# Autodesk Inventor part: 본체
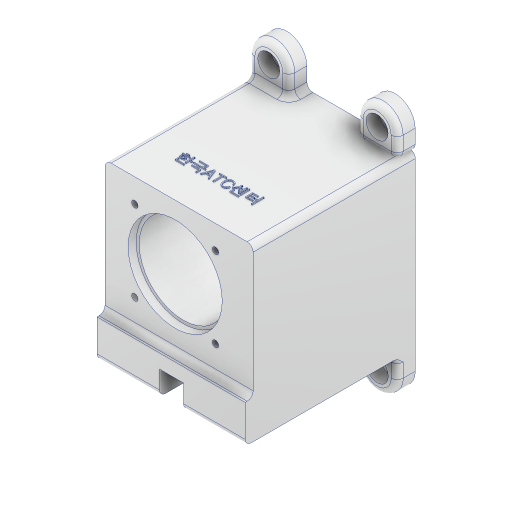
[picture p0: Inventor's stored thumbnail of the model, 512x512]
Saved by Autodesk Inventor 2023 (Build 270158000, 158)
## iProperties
Created: 2024-11
Part Number: 본체
Material: 알루미늄 6061
Document SubType Name: Modeling
Designer: home
Density: 2.7 g/cm^3
Appearance: 알루미늄 - 평지
Mass: 1097.44 g
Surface Area: 539.9 cm^2
Volume: 406.46 cm^3
Author: home
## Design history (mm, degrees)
sketch "스케치10"
  geometry: L1 (-37, 42.5)-(37, 42.5); L2 (37, 42.5)-(37, -42.5); L3 (37, -42.5)-(-37, -42.5); L4 (-37, -42.5)-(-37, 42.5); L5 (-37, 42.5)-(37, -42.5); L6 (37, 42.5)-(-37, -42.5); 1 further point
  constraints: 12 end point, 2 midpoint, 2 parallel, 1 horizontal, 1 perpendicular
  dimensions: "d43" = 74 distance of L1.start L1.end; "d44" = 85 distance of L3.end L1.start
extrude "돌출8" new body sketch "스케치10" stored distance "d45" = 85; taper "d46" = 0 deg
sketch "스케치11"
  geometry: L1 (85, 85)-(0, 85) reference; L2 (0, 0)-(0, 85) reference; L3 (0, 85)-(4, 85); L4 (4, 85)-(4, 19); L5 (4, 19)-(0, 19); L6 (0, 19)-(0, 85); L7 (0, 85)-(4, 19); L8 (4, 85)-(0, 19); 4 further points
  constraints: 12 end point, 2 midpoint, 2 parallel, 1 horizontal, 1 perpendicular
  dimensions: "d47" = 4 distance of L1.end L3.end; "d48" = 66 distance of L3.end L4.end
extrude "돌출9" cut sketch "스케치11" distance "d49" = 77; taper "d50" = 0 deg
sketch "스케치31"
  geometry: C1 r 23.5 at (35.036, 34.068); 1 further point
  constraints: 1 centre point
  dimensions: "d164" = 47 diameter of C1
extrude "돌출21" cut sketch "스케치31" distance "d165" = 4; taper "d166" = 0 deg
sketch "스케치32"
  geometry: C1 r 23.5 at (0, 0) reference; C2 r 22 at (0, 0); 1 further point
  constraints: 1 centre point, 1 coincident
  dimensions: "d168" = 44 diameter of C2
extrude "돌출22" cut sketch "스케치32" distance "d169" = 40; taper "d170" = 0 deg
sketch "스케치35"
  geometry: C1 r 22 at (0, 0) reference; C2 r 17.5 at (0, 0); 1 further point
  constraints: 1 centre point, 1 coincident
  dimensions: "d175" = 35 diameter of C2
extrude "돌출24" cut sketch "스케치35" distance "d176" = 11; taper "d177" = 0 deg
sketch "스케치38"
  geometry: L1 (37, -42.5)-(37, 42.5) reference; L2 (-16.907, 52.568)-(-16.907, 42.568); L3 (-16.907, 42.568)-(-36.907, 42.568); L4 (-36.907, 42.568)-(-36.907, 52.568); L5 (-16.907, 62.568)-(-36.907, 42.568); L6 (-36.907, 62.568)-(-26.907, 52.568); L7 (-19.836, 45.497)-(-16.907, 42.568); L8 (37, 42.5)-(-37, 42.5) reference; L9 (37, 62.5)-(37.204, 62.5); L10 (37.204, 52.5)-(37.204, 42.5); L11 (37.204, 42.5)-(17.204, 42.5); L12 (17.204, 42.5)-(17.204, 52.5); L13 (17.204, 62.5)-(37.204, 42.5); L14 (37.204, 62.5)-(17.204, 42.5); A1 r 10 centre (-26.907, 52.568) between (-16.907, 52.568) and (-36.907, 52.568); A2 r 10 centre (27.204, 52.5) between (37.204, 52.5) and (17.204, 52.5); A3 r 10 centre (27.204, 52.5) between (26.037, 42.568) and (27.204, 42.5); 4 further points
  constraints: 24 end point, 6 point on circle, 5 midpoint, 3 centre point, 3 parallel, 3 point on line, 2 coincident, 1 horizontal, 1 perpendicular
  dimensions: "d194" = 20 distance of L6.start L5.start; "d195" = 20 distance of L5.start L2.end; "d196" = 20 diameter of A1; "d197" = 20 distance of L13.start L9.end; "d198" = 20 distance of L9.end L10.end
sketch "스케치36"
  geometry: C1 r 17.5 at (0, 0) reference; C2 r 15 at (0, 0); 1 further point
  constraints: 1 centre point, 1 coincident
  dimensions: "d178" = 30 diameter of C2
extrude "돌출25" cut sketch "스케치36" distance "d179" = 4; taper "d180" = 0 deg
sketch "스케치37"
  geometry: L1 (35.036, 62.568)-(35.036, 5.568); L2 (35.036, 34.068)-(14.884, 54.22); L3 (35.036, 34.068)-(55.189, 54.22); L4 (35.036, 34.068)-(14.884, 13.915); L5 (35.036, 34.068)-(55.624, 13.48); C1 r 23.5 at (35.036, 34.068) reference; A1 r 28.5 centre (35.036, 34.068) between (35.036, 62.568) and (35.036, 5.568); 5 further points
  constraints: 10 end point, 6 point on circle, 4 coincident, 1 centre point, 1 point on line, 1 vertical
  dimensions: "d181" = 57 diameter of A1; "d182" = 45 deg angle of L1 L2; "d183" = 45 deg angle of L3 L1; "d184" = 90 deg angle of L5 L4; "d185" = 45 deg angle of L1 L4
hole "구멍8" sketch "스케치37" at (14.884, 54.22), (55.189, 54.22), (14.884, 13.915), (55.189, 13.915) diameter "d186" = 3.242; stored, may be unused: countersink angle "d190" = 90 deg, drill point angle "d192" = 118 deg; dims "d187" = 8, "d188" = 4, "d189" = 2, "d191" = 10
extrude "돌출26" join sketch "스케치38" distance "d200" = 9; taper "d201" = 0 deg
sketch "스케치39"
  geometry: A1 r 10 centre (26.907, 52.568) between (36.907, 52.568) and (16.907, 52.568) reference; 2 further points
  constraints: 1 coincident
sketch "스케치40"
  geometry: A1 r 10 centre (-27.204, 52.5) between (-17.204, 52.5) and (-37.204, 52.5) reference; 2 further points
  constraints: 1 coincident
hole "구멍9" sketch "스케치40" at (-27.204, 52.5) diameter "d202" = 3.242; stored, may be unused: countersink angle "d206" = 90 deg, drill point angle "d208" = 0 deg; dims "d203" = 8, "d204" = 11, "d205" = 6.6, "d207" = 6.6
hole "구멍10" sketch "스케치39" diameter "d209" = 3.242; stored, may be unused: countersink angle "d213" = 90 deg, drill point angle "d215" = 0 deg; dims "d210" = 8, "d211" = 11, "d212" = 6.6, "d214" = 6.6
fillet "모깎기11" dims "d216" = 3
sketch "스케치45"
  geometry: 3 further points
  constraints: 1 vertical alignment, 1 other
  dimensions: "d242" = 20 vertical distance of point (74, 0) point (37, 20)
feature "엠보싱3" sketch "스케치45" dims "d43" = 74, "d44" = 85, "d243" = 0.5, "d244" = 0
sketch "스케치46"
  geometry: L1 (-37, -42.5)-(37, -42.5) reference; L2 (17.204, 52.5)-(17.204, 42.5) reference; L3 (37, -42.5)-(-37, -42.5) reference; L4 (17.204, -62.5)-(17, -62.5); L5 (17, -52.5)-(17, -42.5); L6 (17, -42.5)-(37, -42.5); L7 (37, -42.5)-(37, -52.5); L8 (17, -62.5)-(37, -42.5); L9 (37, -62.5)-(27, -52.5); L10 (19.929, -45.429)-(17, -42.5); L11 (-37, -52.5)-(-37, -42.5); L12 (-37, -42.5)-(-17, -42.5); L13 (-17, -42.5)-(-17, -52.5); L14 (-17, -62.5)-(-37, -42.5); L15 (-37, -62.5)-(-17, -42.5); A1 r 10 centre (27, -52.5) between (17, -52.5) and (37, -52.5); A2 r 10 centre (-27, -52.5) between (-37, -52.5) and (-17, -52.5); 4 further points
  constraints: 24 end point, 4 midpoint, 4 point on circle, 3 parallel, 2 centre point, 2 coincident, 2 point on line, 1 horizontal, 1 perpendicular
  dimensions: "d249" = 20 distance of L9.start L4.end; "d250" = 20 distance of L4.end L5.end; "d251" = 20 diameter of A1; "d252" = 20 distance of L14.start L15.start; "d253" = 20 distance of L1.start L15.start; "d254" = 20 diameter of A2
extrude "돌출29" join sketch "스케치46" distance "d255" = 9; taper "d256" = 0 deg
sketch "스케치47"
  geometry: A1 r 10 centre (-27, -52.5) between (-37, -52.5) and (-17, -52.5) reference; 2 further points
  constraints: 1 coincident
sketch "스케치48"
  geometry: A1 r 10 centre (27, -52.5) between (17, -52.5) and (37, -52.5) reference; 2 further points
  constraints: 1 coincident
hole "구멍13" sketch "스케치48" at (27, -52.5) diameter "d257" = 3.242; stored, may be unused: countersink angle "d261" = 90 deg, drill point angle "d263" = 0 deg; dims "d258" = 8, "d259" = 11, "d260" = 6.6, "d262" = 6.6
hole "구멍14" sketch "스케치47" diameter "d264" = 3.242; stored, may be unused: countersink angle "d268" = 90 deg, drill point angle "d270" = 0 deg; dims "d265" = 8, "d266" = 11, "d267" = 6.6, "d269" = 6.6
fillet "모깎기13" dims "d271" = 3
fillet "모깎기14" dims "d272" = 3
fillet "모깎기15" dims "d273" = 3
sketch "스케치49"
  geometry: L1 (14, -42.5)-(-14, -42.5) reference; L2 (-5.782, -42.5)-(-5.782, -30.5); L3 (-5.782, -30.5)-(6.218, -30.5); L4 (6.218, -30.5)-(6.218, -42.5); 1 further point
  constraints: 6 end point, 3 perpendicular, 2 point on line
  dimensions: "d277" = 12 distance of L2.end L3.end; "d278" = 12 distance of L3.end L4.end
extrude "돌출30" cut sketch "스케치49" distance "d274" = 100; taper "d275" = 0 deg
fillet "모깎기16" dims "d276" = 3
fillet "모깎기17" dims "d279" = 3
fillet "모깎기18" dims "d280" = 3
node "솔리드3"
feature "A9D066F2-1C7D-4E18-AEED-F7BC21143FA4" dims "d186" = 3.242, "d187" = 8, "d188" = 4, "d189" = 2, "d190" = 90 deg, "d191" = 10, "d192" = 118 deg
